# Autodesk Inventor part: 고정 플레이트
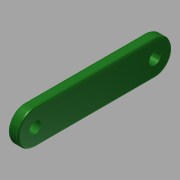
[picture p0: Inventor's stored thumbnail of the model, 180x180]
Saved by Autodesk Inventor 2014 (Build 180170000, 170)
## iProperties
Created: 2017-04
Part Number: 고정 플레이트
Material: 스테인리스강
Document SubType Name: Modeling
Designer: mduedu
Density: 8.08 g/cm^3
Appearance: 매끄러움 - 짙은 산림 녹색
Mass: 9.86033 g
Surface Area: 11.4535 cm^2
Volume: 1.22034 cm^3
Author: mduedu
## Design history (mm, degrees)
sketch "스케치1"
  geometry: L1 (0, 17.5)-(0, -17.5); L2 (-5, 17.5)-(-5, -17.5); L3 (5, -17.5)-(5, 17.5); A1 r 5 centre (0, 17.5) between (5, 17.5) and (-5, 17.5); A2 r 5 centre (0, -17.5) between (-5, -17.5) and (5, -17.5); 2 further points
  constraints: 6 end point, 4 point on circle, 4 tangent, 3 coincident, 2 centre point, 1 midpoint, 1 parallel, 1 vertical
  dimensions: "d0" = 35 distance of L1.start L1.end; "d1" = 5 radius of A2
extrude "돌출1" new body sketch "스케치1" distance "d2" = 3; taper "d3" = 0 deg
fillet "모깎기1" dims "d4" = 0.5
sketch "스케치2"
  geometry: A1 r 5 centre (-17.5, 0) between (-17.5, 5) and (-17.5, -5) reference; A2 r 5 centre (17.5, 0) between (17.5, -5) and (17.5, 5) reference; 3 further points
  constraints: 2 coincident
sketch "스케치3"
  geometry: 3 further points
  constraints: 3 other
hole "구멍1" sketch "스케치3" at (-17.5, 0), (17.5, 0) diameter "d5" = 3.4; stored, may be unused: countersink angle "d9" = 90 deg, drill point angle "d11" = 0 deg; dims "d6" = 6, "d7" = 4, "d8" = 2, "d10" = 8
node "솔리드1"
